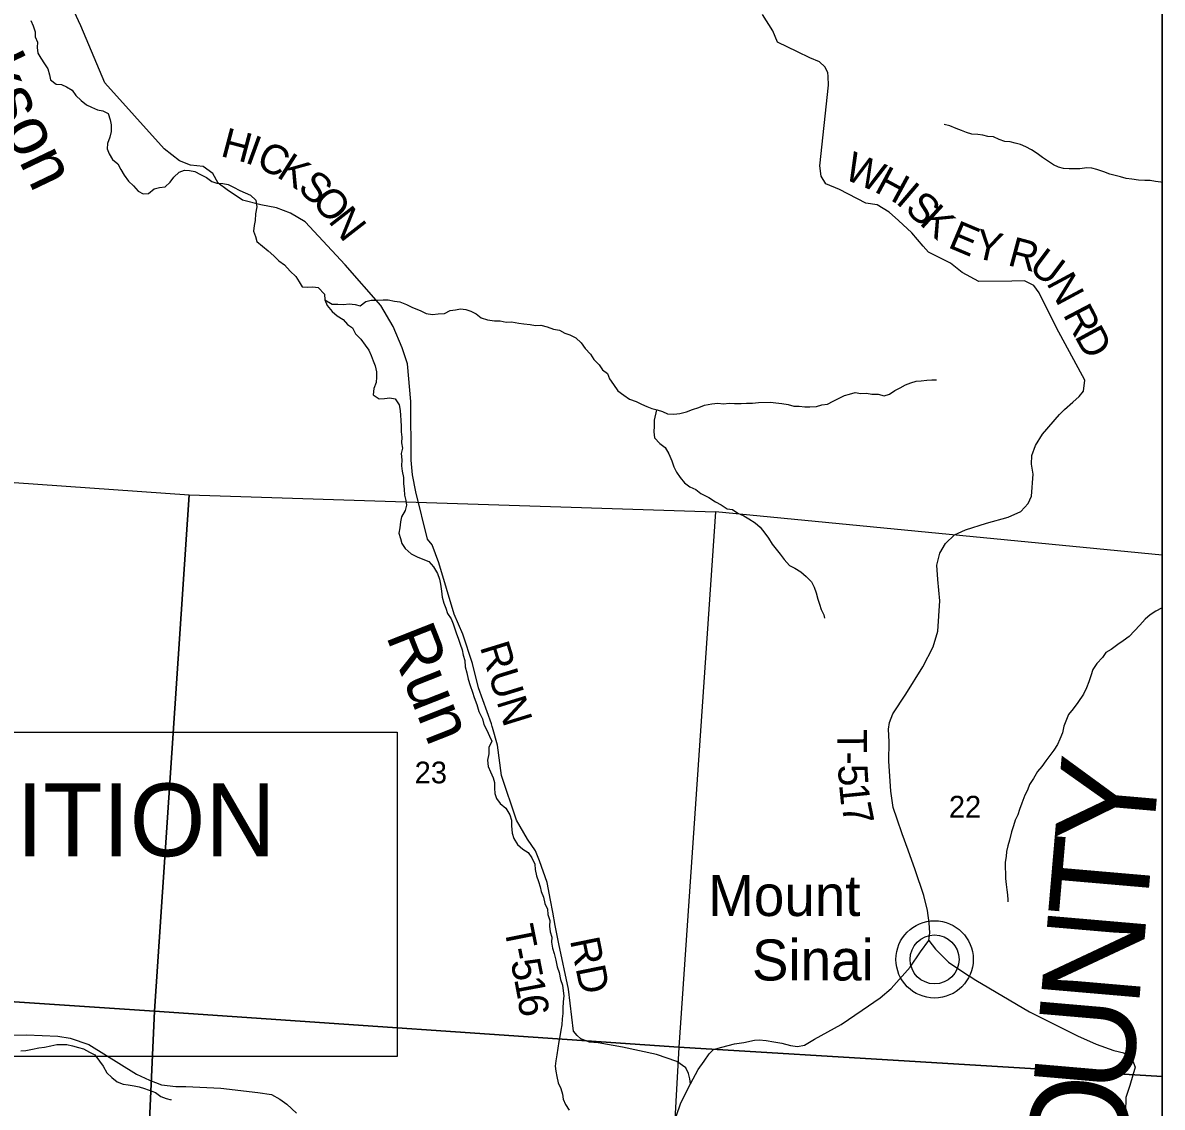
# Model space of a CAD drawing. Extents: x 5.6 to 39.6, y 0.7 to 22.7.
# Drawn here: x 12.858 to 15.052, y 15.903 to 17.991 of the extents above; entities that cross this region are included whole.
import ezdxf

# ---------------------------------------------------------------- set-up
doc = ezdxf.new("R2010")
doc.units = 0
doc.layers.add('Default', color=7, linetype='Continuous')
doc.layers.add('SH_Data', color=7, linetype='Continuous')

msp = doc.modelspace()

# ---------------------------------------------------------------- linework, layer by layer
at = {"layer": 'Default'}
for p, q in [((15.0518, 15.9625), (15.0518, 16.9663)), ((15.0518, 14.9373), (15.0518, 15.9625))]:
    msp.add_line(p, q, dxfattribs=at)
for points in [[(8.2518, 18.5322), (8.2518, 14.9074), (15.0518, 14.9074), (15.0518, 18.0251)], [(8.2518, 18.5322), (8.2518, 14.9074), (15.0518, 14.9074), (15.0518, 18.0251)], [(8.2518, 18.5322), (8.2518, 14.9074), (15.0518, 14.9074), (15.0518, 18.0251)], [(13.7619, 16.6361), (13.7603, 16.6414), (13.7354, 16.7106), (13.7239, 16.7577), (13.7057, 16.8144), (13.6885, 16.8528), (13.6592, 16.9513), (13.6461, 16.9859), (13.6375, 16.9973), (13.6149, 17.0882), (13.6083, 17.1212), (13.6062, 17.1493), (13.6053, 17.2621), (13.5986, 17.3346), (13.5885, 17.3658), (13.571, 17.4065), (13.5474, 17.4473), (13.4789, 17.5255), (13.4018, 17.6083), (13.3738, 17.6247), (13.3466, 17.6348), (13.3167, 17.641), (13.2812, 17.6499), (13.2514, 17.6699), (13.2344, 17.6829), (13.2239, 17.7015), (13.2055, 17.7145), (13.1812, 17.7173), (13.1597, 17.7254), (13.1303, 17.7487), (13.0163, 17.8758), (12.9698, 17.9855), (12.9223, 18.0883)], [(12.8736, 17.9959), (12.8783, 17.9856), (12.8818, 17.9737), (12.882, 17.9643), (12.8863, 17.9543), (12.8857, 17.9437), (12.8874, 17.933), (12.8932, 17.9234), (12.8998, 17.9126), (12.9064, 17.903), (12.9099, 17.8912), (12.9119, 17.8813), (12.9227, 17.8734), (12.9329, 17.8724), (12.9427, 17.8684), (12.9531, 17.8614), (12.9605, 17.8517), (12.9705, 17.8416), (12.9809, 17.8334), (12.9907, 17.8291), (13.0023, 17.8235), (13.0121, 17.8218), (13.0229, 17.8166), (13.0268, 17.8047), (13.0281, 17.7952), (13.0286, 17.7823), (13.0261, 17.771), (13.0213, 17.759), (13.021, 17.7487), (13.0246, 17.7388), (13.0312, 17.7284), (13.0412, 17.7198), (13.047, 17.7091), (13.0536, 17.6983), (13.062, 17.6867), (13.0717, 17.6774), (13.0802, 17.6674), (13.0903, 17.6622), (13.1001, 17.6627), (13.1113, 17.6716), (13.1216, 17.674), (13.1326, 17.6753), (13.1423, 17.6846), (13.1493, 17.6943), (13.1594, 17.7039), (13.1693, 17.7075), (13.1792, 17.7073), (13.1893, 17.7052), (13.2002, 17.6992), (13.2122, 17.6936), (13.2222, 17.6858), (13.232, 17.6826), (13.2433, 17.682), (13.2539, 17.6798), (13.2636, 17.6751), (13.2764, 17.6687), (13.2966, 17.6592), (13.3066, 17.6498), (13.309, 17.6369), (13.3064, 17.6233), (13.3054, 17.6108), (13.3036, 17.601), (13.3026, 17.59), (13.3062, 17.58), (13.309, 17.5705), (13.3198, 17.5611), (13.3309, 17.5522), (13.3417, 17.5425), (13.3513, 17.5328), (13.3621, 17.5253), (13.3728, 17.5129), (13.3836, 17.5028), (13.3902, 17.4928), (13.396, 17.4832), (13.4062, 17.4822), (13.4165, 17.4831), (13.427, 17.4818), (13.4389, 17.469), (13.4398, 17.458)], [(14.6025, 16.2245), (14.6045, 16.2389), (14.6031, 16.2582), (14.5998, 16.2818), (14.5928, 16.311), (14.576, 16.3601), (14.563, 16.3985), (14.551, 16.4297), (14.5414, 16.4582), (14.5339, 16.4803), (14.5292, 16.5118), (14.5253, 16.5695), (14.5263, 16.6067), (14.5246, 16.631), (14.5269, 16.6443), (14.5331, 16.6606), (14.5583, 16.6987), (14.5912, 16.7513), (14.6107, 16.7899), (14.6196, 16.8198), (14.6237, 16.8783), (14.6198, 16.9197), (14.6181, 16.947), (14.6235, 16.9701), (14.6346, 16.9887), (14.6518, 17.0053), (14.673, 17.015), (14.7136, 17.0281), (14.7554, 17.0396), (14.7793, 17.0504), (14.7938, 17.0659), (14.8003, 17.0799), (14.8032, 17.122), (14.8003, 17.1414), (14.8011, 17.1585), (14.8081, 17.1774), (14.8211, 17.199), (14.8543, 17.2371), (14.8638, 17.2466), (14.8794, 17.2609), (14.892, 17.2718), (14.9, 17.282), (14.9031, 17.3033), (14.8484, 17.4042), (14.8147, 17.4715), (14.8046, 17.4856), (14.7869, 17.4945), (14.7622, 17.4938), (14.699, 17.4931), (14.6669, 17.5107), (14.6439, 17.5283), (14.6201, 17.541), (14.6016, 17.5498), (14.5915, 17.5612), (14.5696, 17.5872), (14.544, 17.6105), (14.5263, 17.6269), (14.5033, 17.6407), (14.481, 17.6442), (14.4304, 17.6707), (14.404, 17.6811), (14.395, 17.696), (14.3924, 17.7161), (14.4093, 17.8713), (14.409, 17.888), (14.4079, 17.8959), (14.4023, 17.9066), (14.3921, 17.9161), (14.3732, 17.9242), (14.3498, 17.9358), (14.3113, 17.9538), (14.302, 17.9761), (14.2824, 18.0075)], [(15.0518, 17.6837), (15.049, 17.6844), (15.0388, 17.6861), (15.0283, 17.6875), (15.0184, 17.6877), (15.0063, 17.6884), (14.9931, 17.6906), (14.9822, 17.6916), (14.9713, 17.6949), (14.9611, 17.6974), (14.9509, 17.7002), (14.9393, 17.7047), (14.9261, 17.7091), (14.9163, 17.7116), (14.9065, 17.7122), (14.8932, 17.7102), (14.883, 17.7105), (14.8724, 17.7099), (14.8618, 17.7106), (14.852, 17.7131), (14.8423, 17.7182), (14.8326, 17.7245), (14.8214, 17.7319), (14.8109, 17.7394), (14.8001, 17.7465), (14.7893, 17.7528), (14.7791, 17.7572), (14.7686, 17.7597), (14.7588, 17.7622), (14.749, 17.7628), (14.7377, 17.7664), (14.7272, 17.7716), (14.7163, 17.7726), (14.7065, 17.7751), (14.6966, 17.7761), (14.6853, 17.7767), (14.6752, 17.7803), (14.6654, 17.784), (14.6549, 17.7876), (14.6429, 17.7932), (14.6323, 17.7953), (14.632, 17.7957)], [(13.4398, 17.458), (13.4444, 17.4469), (13.4536, 17.4353), (13.4637, 17.4271), (13.4749, 17.42), (13.4834, 17.4103), (13.4931, 17.4041), (13.4989, 17.3926), (13.5093, 17.3825), (13.5173, 17.3709), (13.5243, 17.3609), (13.529, 17.3509), (13.5329, 17.3402), (13.5365, 17.3306), (13.5393, 17.3196), (13.539, 17.3093), (13.5384, 17.2987), (13.534, 17.2871), (13.533, 17.275), (13.5441, 17.2671), (13.5548, 17.268), (13.5646, 17.269), (13.5752, 17.2676), (13.5829, 17.2556), (13.5845, 17.245), (13.5851, 17.2355), (13.586, 17.226), (13.5865, 17.2138), (13.5866, 17.2036), (13.5879, 17.1937), (13.5873, 17.1823), (13.589, 17.1721), (13.5865, 17.1619), (13.5881, 17.1501), (13.5874, 17.138), (13.5887, 17.1281), (13.5911, 17.1159), (13.5912, 17.1045), (13.5925, 17.0935), (13.5934, 17.0821), (13.5958, 17.0718), (13.5971, 17.0623), (13.5942, 17.0521), (13.5875, 17.0401), (13.5854, 17.0303), (13.584, 17.0189), (13.5819, 17.0087), (13.5851, 16.9984), (13.5879, 16.9885), (13.5945, 16.9789), (13.606, 16.9688), (13.6172, 16.9632), (13.6281, 16.9588), (13.6397, 16.9543), (13.649, 16.9439), (13.6566, 16.9312), (13.6602, 16.9198), (13.6622, 16.9102), (13.6642, 16.8969), (13.6654, 16.8851), (13.669, 16.8737), (13.6725, 16.8641), (13.6761, 16.8538), (13.6827, 16.8434), (13.687, 16.8338), (13.6923, 16.817), (13.6973, 16.8048), (13.7005, 16.7948), (13.7041, 16.7841), (13.7061, 16.7738), (13.7093, 16.7632), (13.7102, 16.7514), (13.7133, 16.7396), (13.7157, 16.7277), (13.7192, 16.7155), (13.7242, 16.7025), (13.727, 16.6922), (13.7324, 16.6788), (13.7359, 16.6651), (13.7431, 16.6513), (13.7459, 16.6402), (13.7513, 16.6291), (13.7568, 16.6176), (13.7611, 16.608), (13.7555, 16.5956), (13.7552, 16.5839), (13.7527, 16.5714), (13.7543, 16.5596), (13.7586, 16.5493), (13.7641, 16.5378), (13.7661, 16.5283), (13.7663, 16.5176), (13.7668, 16.5074), (13.7704, 16.4978), (13.777, 16.4882), (13.7885, 16.4788), (13.7962, 16.4665), (13.7993, 16.4558), (13.7991, 16.4448), (13.8003, 16.4312), (13.8038, 16.4205)], [(13.4398, 17.458), (13.4536, 17.4493), (13.4646, 17.4498), (13.4759, 17.4492), (13.4869, 17.4501), (13.4979, 17.4487), (13.508, 17.4466), (13.5185, 17.4547), (13.5291, 17.4571), (13.539, 17.4573), (13.5519, 17.4578), (13.5617, 17.4579), (13.5741, 17.4554), (13.5843, 17.454), (13.5967, 17.4488), (13.6087, 17.4429), (13.6233, 17.4372), (13.6346, 17.4313), (13.6467, 17.4299), (13.658, 17.4308), (13.6698, 17.4316), (13.6813, 17.4371), (13.6912, 17.4384), (13.7007, 17.4404), (13.7113, 17.4394), (13.721, 17.4362), (13.7308, 17.431), (13.7408, 17.4232), (13.7528, 17.4196), (13.7661, 17.4174), (13.7774, 17.4175), (13.7887, 17.415), (13.7993, 17.4155), (13.8129, 17.4133), (13.8227, 17.4116), (13.8348, 17.4105), (13.8454, 17.4088), (13.8556, 17.4089), (13.8677, 17.406), (13.8797, 17.4016), (13.8914, 17.3998), (13.9015, 17.3939), (13.9116, 17.3903), (13.9232, 17.3847), (13.9329, 17.3754), (13.941, 17.3642), (13.9509, 17.3533), (13.9575, 17.3433), (13.9679, 17.3329), (13.9741, 17.3229), (13.9842, 17.3158), (13.9877, 17.3055), (13.9954, 17.2951), (14.0035, 17.2828), (14.0154, 17.2742), (14.0262, 17.2667), (14.0394, 17.2619), (14.0491, 17.2571), (14.0596, 17.2527), (14.0694, 17.2487), (14.0792, 17.2458), (14.0897, 17.2426), (14.0994, 17.2385), (14.1119, 17.2375), (14.1233, 17.2392), (14.1363, 17.2423), (14.1477, 17.2466), (14.1599, 17.2509), (14.1706, 17.2548), (14.1847, 17.2579), (14.1965, 17.2588), (14.2074, 17.2578), (14.2184, 17.259), (14.2286, 17.2581), (14.2411, 17.2582), (14.2514, 17.2587), (14.2628, 17.2592), (14.2745, 17.2605), (14.298, 17.2607), (14.3078, 17.2597), (14.3195, 17.2583), (14.332, 17.2562), (14.3425, 17.2533), (14.3531, 17.253), (14.3641, 17.252), (14.3736, 17.2522), (14.3864, 17.2523), (14.3967, 17.2555), (14.4077, 17.2571), (14.4181, 17.263), (14.4296, 17.2684), (14.4399, 17.2739), (14.4498, 17.2763), (14.4609, 17.2795), (14.4715, 17.2777), (14.4824, 17.2779), (14.4926, 17.2761), (14.5051, 17.2766), (14.5164, 17.2729), (14.5267, 17.2765), (14.5371, 17.2831)], [(14.5371, 17.2831), (14.5471, 17.2886), (14.5574, 17.2944), (14.5681, 17.298), (14.578, 17.3012), (14.5875, 17.3021), (14.5989, 17.3033), (14.6084, 17.3039), (14.6171, 17.3037)], [(14.0781, 17.2461), (14.0738, 17.2262), (14.0735, 17.2148), (14.0729, 17.2039), (14.0745, 17.1921), (14.0849, 17.1816), (14.0946, 17.1734), (14.1022, 17.1611), (14.108, 17.1477), (14.1119, 17.1362), (14.1166, 17.1263), (14.1236, 17.1155), (14.1324, 17.1058), (14.1425, 17.098), (14.1537, 17.0924), (14.1638, 17.085), (14.1788, 17.0775), (14.1918, 17.0692), (14.2027, 17.0633), (14.2142, 17.0558), (14.2248, 17.0541), (14.2349, 17.0474), (14.2461, 17.0419), (14.2558, 17.0363), (14.2682, 17.0285), (14.2778, 17.0199), (14.287, 17.0087), (14.294, 16.9987), (14.3006, 16.9875), (14.3083, 16.9775), (14.316, 16.9679), (14.3241, 16.9578), (14.3345, 16.9466), (14.3446, 16.9411), (14.3558, 16.9344), (14.3666, 16.9254), (14.3766, 16.9149), (14.3816, 16.9046), (14.3856, 16.8939), (14.3887, 16.8813), (14.3919, 16.8717), (14.3955, 16.8618), (14.4005, 16.8514), (14.4015, 16.845)], [(15.0518, 16.9663), (14.1916, 17.0496), (14.121, 16.0188), (15.0518, 15.9625)], [(15.0518, 16.8649), (15.0503, 16.864), (15.0392, 16.8585), (15.0288, 16.8515), (15.0191, 16.843), (15.009, 16.8315), (14.9986, 16.8204), (14.9881, 16.8096), (14.9765, 16.8011), (14.9662, 16.7942), (14.9538, 16.7846), (14.9435, 16.7787), (14.9368, 16.769), (14.926, 16.7579), (14.9185, 16.7463), (14.9141, 16.7342), (14.9108, 16.7222), (14.9063, 16.7105), (14.9, 16.6985), (14.8891, 16.6828), (14.8804, 16.6701), (14.8711, 16.6597), (14.8675, 16.6499), (14.8627, 16.6368), (14.8597, 16.6243), (14.8549, 16.6119), (14.8505, 16.6014), (14.8434, 16.5909), (14.8353, 16.5805), (14.8275, 16.5704), (14.82, 16.5592), (14.8115, 16.5495), (14.804, 16.5364), (14.7965, 16.5248), (14.7925, 16.5139), (14.7873, 16.5038), (14.7817, 16.4887), (14.7769, 16.4767), (14.7736, 16.4662), (14.7688, 16.4557), (14.7656, 16.4451), (14.7619, 16.4334), (14.7581, 16.4176), (14.7549, 16.4063), (14.752, 16.3957), (14.7514, 16.3859), (14.7496, 16.3753), (14.7494, 16.3639), (14.7499, 16.354), (14.7504, 16.3434), (14.7513, 16.332), (14.7526, 16.3221), (14.7539, 16.3119), (14.7548, 16.3024), (14.7547, 16.2986)], [(14.1437, 15.9485), (14.1423, 15.9578), (14.1397, 15.9679), (14.1348, 15.9793), (14.1174, 15.9915), (14.0785, 16.0046), (14.0127, 16.0187), (13.9662, 16.0269), (13.9491, 16.0285), (13.9325, 16.0347), (13.9253, 16.0415), (13.9186, 16.0499), (13.9088, 16.1304), (13.8904, 16.2178), (13.8834, 16.2532), (13.8786, 16.2786), (13.8742, 16.3022), (13.8676, 16.336), (13.8531, 16.3775), (13.8456, 16.3972), (13.8302, 16.4193), (13.8085, 16.4559), (13.7798, 16.5422), (13.7722, 16.6003), (13.7623, 16.6347), (13.7619, 16.6361)], [(13.8038, 16.4205), (13.8108, 16.4093), (13.8208, 16.4004), (13.8309, 16.3937), (13.8382, 16.3837), (13.844, 16.3714), (13.8449, 16.3608), (13.8473, 16.3486), (13.8512, 16.3379), (13.854, 16.3279), (13.8565, 16.3184), (13.8604, 16.3077), (13.8631, 16.2955), (13.8686, 16.2848), (13.8691, 16.2741), (13.873, 16.263), (13.8724, 16.2517), (13.8737, 16.241), (13.8765, 16.2307), (13.8759, 16.2209), (13.8779, 16.2098), (13.8811, 16.1991), (13.8842, 16.1866), (13.8869, 16.1736), (13.8908, 16.1629), (13.8936, 16.1492), (13.8971, 16.1381), (13.8988, 16.1275), (13.8997, 16.1179), (13.8987, 16.1062), (13.898, 16.0941), (13.8978, 16.0835), (13.8968, 16.0736), (13.8958, 16.0619), (13.894, 16.0513), (13.8923, 16.0396), (13.8905, 16.0298), (13.8883, 16.0169), (13.8865, 16.0041), (13.8844, 15.9927), (13.8834, 15.9821), (13.8847, 15.9726), (13.8864, 15.9627), (13.8887, 15.9502), (13.8942, 15.9394), (13.897, 15.9284), (13.8986, 15.9185), (13.9029, 15.9085), (13.9103, 15.8977)], [(14.1164, 15.8856), (14.1249, 15.9118), (14.1437, 15.9485), (14.1586, 15.9761), (14.1701, 15.9916), (14.1796, 16.006), (14.188, 16.0143), (14.2043, 16.0187), (14.2282, 16.025), (14.2461, 16.028), (14.2669, 16.0324), (14.2756, 16.0331), (14.2896, 16.0315), (14.3044, 16.0292), (14.3195, 16.0264), (14.3365, 16.0222), (14.3498, 16.0202), (14.3631, 16.0228), (14.3824, 16.034), (14.4337, 16.0626), (14.474, 16.0901), (14.509, 16.1138), (14.53, 16.1319), (14.5666, 16.173), (14.5864, 16.2022), (14.6025, 16.2245), (14.6156, 16.2077), (14.6401, 16.1825), (14.6817, 16.1552)], [(14.6817, 16.1552), (14.682, 16.155), (14.6933, 16.1477), (14.796, 16.0871), (14.8885, 16.041), (14.9244, 16.0245), (14.9584, 16.0122), (14.9777, 16.0079), (14.9931, 15.9968), (14.9999, 15.9804), (14.9894, 15.9452), (14.9817, 15.9221), (14.9808, 15.8936), (14.9863, 15.8556), (14.9911, 15.8416), (15.0092, 15.8255), (15.0277, 15.8099), (15.0378, 15.7984), (15.0518, 15.7628)], [(12.7928, 16.0422), (12.8652, 16.0429), (12.9258, 16.0399), (12.9492, 16.036), (12.9851, 16.024), (13.0772, 15.9666), (13.1022, 15.9551), (13.1252, 15.9462), (13.1532, 15.9434), (13.1722, 15.9429), (13.2396, 15.9399), (13.3107, 15.9315), (13.3368, 15.9275), (13.3534, 15.9187), (13.3666, 15.9088), (13.3855, 15.892)], [(12.8547, 16.0117), (12.8642, 16.0126), (12.8767, 16.0153), (12.8893, 16.0177), (12.8999, 16.019), (12.9124, 16.0214), (12.9235, 16.0242), (12.9333, 16.0243), (12.9432, 16.0237), (12.9541, 16.0212), (12.9654, 16.0183), (12.9752, 16.0154), (12.9868, 16.0095), (12.9969, 16.004), (13.0057, 15.992), (13.0131, 15.9824), (13.02, 15.9697), (13.0296, 15.9604), (13.04, 15.9518), (13.0513, 15.9474), (13.0611, 15.9464), (13.0724, 15.9443), (13.0826, 15.9425), (13.0924, 15.9393), (13.1138, 15.9316), (13.1243, 15.9241), (13.134, 15.9198), (13.1442, 15.9176), (13.1434, 15.9177)], [(15.0518, 15.9625), (14.121, 16.0188), (14.0665, 15.031), (15.0518, 14.9373)]]:
    msp.add_lwpolyline(points, dxfattribs=at)
for points in [[(12.2127, 17.1504), (13.1788, 17.0823), (13.1121, 16.0885), (12.1494, 16.1525)], [(13.1788, 17.0823), (14.1916, 17.0496), (14.121, 16.0188), (13.1121, 16.0885)], [(12.1494, 16.1525), (13.1121, 16.0885), (13.0667, 15.1046), (12.9641, 15.1117), (12.0885, 15.1757)], [(13.1121, 16.0885), (14.121, 16.0188), (14.0665, 15.031), (14.0218, 15.0338), (13.0667, 15.1046)]]:
    msp.add_lwpolyline(points, close=True, dxfattribs=at)
for radius in [0.0744, 0.0472]:
    msp.add_circle((14.6136, 16.1879), radius, dxfattribs=at)
at = {"layer": 'SH_Data'}
msp.add_line((15.0518, 21.7074), (15.0518, 14.7074), dxfattribs=at)
msp.add_lwpolyline([(11.4381, 16.6256), (13.5787, 16.6256), (13.5787, 16.0006), (11.4381, 16.0006)], close=True, dxfattribs=at)

# ---------------------------------------------------------------- texts
at = {"layer": 'Default'}
for s, height, rotation, p in [('Hickson', 0.09471, 295.6089, (12.686, 18.0681)), ('H', 0.0568, 345.278, (13.237, 17.7352)), ('I', 0.0568, 339.9198, (13.284, 17.7229)), ('C', 0.0568, 333.7298, (13.3045, 17.7155)), ('K', 0.0568, 327.4991, (13.3449, 17.6957)), ('W', 0.0568, 337.189, (14.436, 17.6923)), ('S', 0.0568, 318.8035, (13.3852, 17.6702)), ('H', 0.0568, 331.623, (14.4954, 17.6674)), ('I', 0.0568, 319.6087, (14.5368, 17.6454)), ('O', 0.0568, 310.9378, (13.4126, 17.6464)), ('S', 0.0568, 317.5911, (14.5542, 17.6307)), ('N', 0.0568, 307.8489, (13.4449, 17.6093)), ('K', 0.0568, 317.603, (14.5825, 17.6048)), ('E', 0.0568, 337.1525, (14.6372, 17.5597)), ('Y', 0.0568, 347.4952, (14.687, 17.5398)), ('R', 0.0568, 345.1307, (14.7522, 17.5252)), ('U', 0.0568, 323.2379, (14.7922, 17.5157)), ('N', 0.0568, 298.2383, (14.828, 17.4907)), ('R', 0.0568, 297.7032, (14.8599, 17.4301)), ('D', 0.0568, 298.5674, (14.882, 17.3879)), ('Run', 0.0947, 291.5265, (13.5568, 16.8112)), ('RUN', 0.05682, 287.0808, (13.7378, 16.7898)), ('T', 0.0568, 270.1286, (14.4266, 16.6315)), ('-', 0.0568, 271.1572, (14.4267, 16.5878)), ('23', 0.04182, 0, (13.6127, 16.5269)), ('Y', 0.1894, 85.063, (15.033, 16.4014)), ('5', 0.0568, 273.4762, (14.4273, 16.562)), ('1', 0.0568, 275.6567, (14.4296, 16.5247)), ('22', 0.04182, 0, (14.6411, 16.461)), ('7', 0.0568, 281.5463, (14.434, 16.4836)), ('T', 0.1894, 85.063, (15.0208, 16.2605)), ('Mount', 0.07891, 0, (14.1777, 16.2714)), ('T', 0.0568, 281.3015, (13.7844, 16.2488)), ('N', 0.1894, 85.0633, (15.0065, 16.0939)), ('RD', 0.05682, 281.5011, (13.9114, 16.225)), ('Sinai', 0.07891, 0, (14.2619, 16.1473)), ('5', 0.0568, 281.0915, (13.7972, 16.1843)), ('-', 0.0568, 281.2655, (13.7927, 16.2072)), ('1', 0.0568, 280.5823, (13.804, 16.1501)), ('6', 0.0568, 278.7557, (13.8103, 16.1162)), ('U', 0.1894, 85.0609, (14.9921, 15.9274)), ('O', 0.1894, 84.9739, (14.9774, 15.7605))]:
    msp.add_text(s, height=height, rotation=rotation, dxfattribs=at).set_placement(p)
at = {"layer": 'SH_Data'}
msp.add_text('BEGIN ACQUISITION', height=0.14, dxfattribs=at).set_placement((11.4934, 16.3866))

doc.saveas('drawing.dxf')
